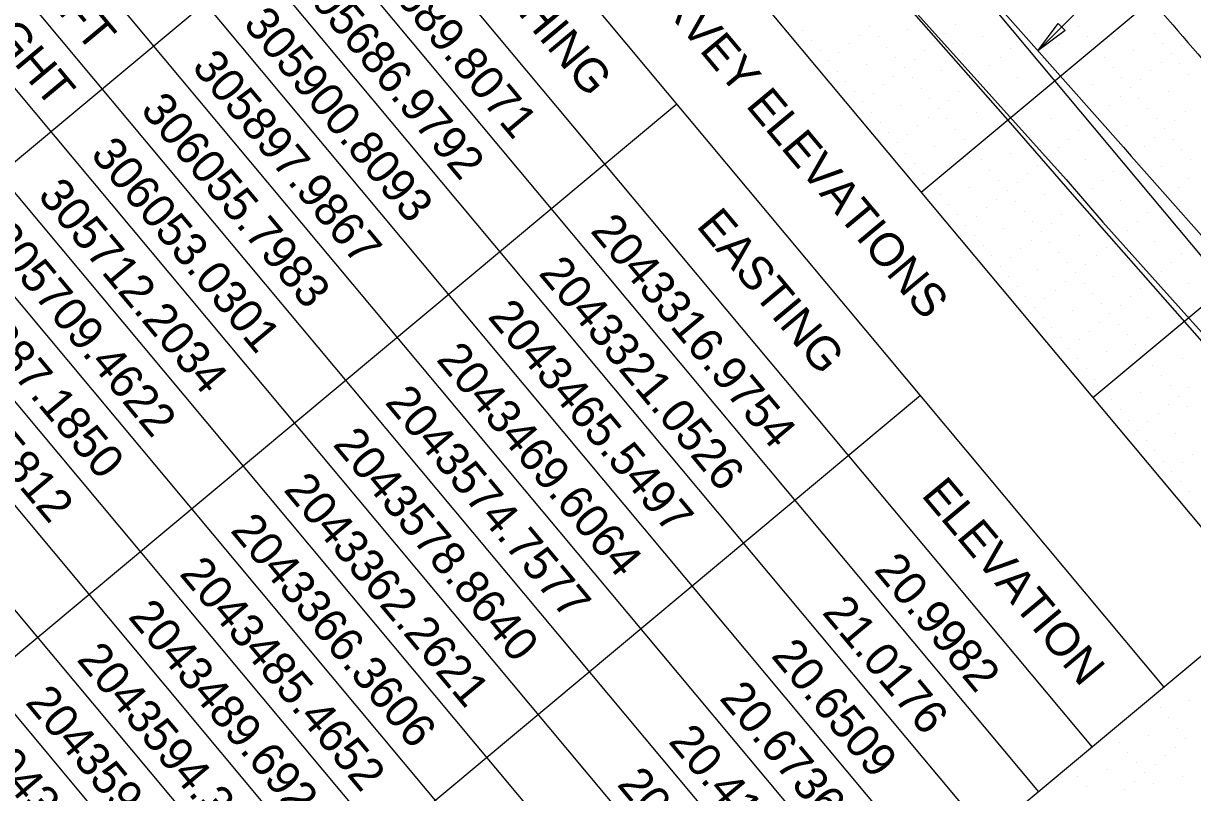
# Model space of a CAD drawing. Extents: x 2042995 to 2043795, y 305365 to 306249.
# Drawn here: x 2043107.3 to 2043194.7, y 305897.9 to 305955.5 of the extents above; entities that cross this region are included whole.
import ezdxf

# ---------------------------------------------------------------- set-up
doc = ezdxf.new("R2010")
doc.units = 0
for name, color, linetype in [('BR_AUTO DIMENSION', 7, 'Continuous'), ('BR_BORDER LINES', 7, 'Continuous'), ('BR_CONCRETE', 7, 'Continuous'), ('BR_EXIST_GROUND_CL', 7, 'Continuous'), ('BR_EXIST_GROUND_LT', 7, 'Continuous'), ('BR_EXIST_GROUND_RT', 7, 'Continuous'), ('BR_GRID DOTS', 7, 'Continuous'), ('BR_GRID LINES', 7, 'Continuous'), ('BR_TABLE LINES', 7, 'Continuous'), ('BR_TEXT', 7, 'Continuous')]:
    doc.layers.add(name, color=color, linetype=linetype)

msp = doc.modelspace()

# ---------------------------------------------------------------- linework, layer by layer
at = {"layer": 'BR_AUTO DIMENSION'}
msp.add_line((2043190.687, 305960.982), (2043183.14, 305953.414), dxfattribs=at)
msp.add_lwpolyline([(2043185.171, 305954.92), (2043183.14, 305953.414), (2043184.64, 305955.449)], close=True, dxfattribs=at)
at = {"layer": 'BR_BORDER LINES'}
for p, q in [((2043123.144, 306004.214), (2043200.067, 305912.112)), ((2043200.067, 305912.112), (2043117.942, 305843.522))]:
    msp.add_line(p, q, dxfattribs=at)
at = {"layer": 'BR_CONCRETE'}
msp.add_spline([(2043139.109, 306017.548), (2043148.199, 306007.16), (2043160.233, 305993.368), (2043172.245, 305979.557), (2043184.234, 305965.727), (2043196.201, 305951.879), (2043208.145, 305938.012), (2043220.067, 305924.126), (2043231.966, 305910.221), (2043243.843, 305896.297), (2043255.698, 305882.355), (2043267.529, 305868.394), (2043279.339, 305854.414), (2043291.126, 305840.415), (2043302.89, 305826.398), (2043314.632, 305812.361), (2043326.352, 305798.306), (2043338.049, 305784.233), (2043349.724, 305770.14), (2043361.376, 305756.029), (2043373.005, 305741.899), (2043384.613, 305727.75), (2043396.197, 305713.582), (2043407.76, 305699.396), (2043419.299, 305685.191), (2043430.817, 305670.967), (2043442.311, 305656.724), (2043453.784, 305642.463), (2043465.234, 305628.182), (2043476.661, 305613.883), (2043488.066, 305599.566), (2043499.448, 305585.229), (2043510.808, 305570.874), (2043522.146, 305556.5), (2043533.461, 305542.107), (2043544.753, 305527.695), (2043547.219, 305524.543)], degree=3, dxfattribs=at)
at = {"layer": 'BR_EXIST_GROUND_CL'}
msp.add_lwpolyline([(2043131.677, 306011.341), (2043140.193, 306001.792), (2043140.699, 306001.23), (2043156.38, 305983.649), (2043157.081, 305982.859), (2043172.95, 305964.927), (2043173.594, 305964.202), (2043189.52, 305946.204), (2043190.108, 305945.543), (2043206.09, 305927.482)], dxfattribs=at)
at = {"layer": 'BR_EXIST_GROUND_LT'}
msp.add_lwpolyline([(2043127.956, 306008.234), (2043136.17, 305998.877), (2043139.136, 305995.79), (2043151.989, 305981.161), (2043154.962, 305977.692), (2043168.609, 305962.472), (2043171.467, 305959.143), (2043185.235, 305943.789), (2043187.984, 305940.592), (2043201.866, 305925.112), (2043204.513, 305922.037), (2043218.502, 305906.439), (2043218.632, 305906.288), (2043219.569, 305905.47), (2043220.034, 305904.951), (2043224.372, 305899.652), (2043230.892, 305893.533)], dxfattribs=at)
at = {"layer": 'BR_EXIST_GROUND_RT'}
msp.add_lwpolyline([(2043127.871, 306008.162), (2043135.626, 305999.492), (2043140.757, 305993.755), (2043152.231, 305980.926), (2043152.788, 305980.304), (2043164.384, 305967.114), (2043169.234, 305961.496), (2043181.072, 305948.031), (2043185.685, 305942.691), (2043197.744, 305928.975)], dxfattribs=at)
at = {"layer": 'BR_GRID DOTS'}
for p, q in [((2043164.169, 305955.093), (2043164.169, 305955.093)), ((2043165.578, 305954.966), (2043165.578, 305954.966)), ((2043169.803, 305954.587), (2043169.803, 305954.587)), ((2043170.571, 305955.228), (2043170.571, 305955.228)), ((2043173.388, 305954.975), (2043173.388, 305954.975)), ((2043176.205, 305954.722), (2043176.205, 305954.722)), ((2043176.973, 305955.363), (2043176.973, 305955.363)), ((2043182.607, 305954.857), (2043182.607, 305954.857)), ((2043186.191, 305955.245), (2043186.191, 305955.245)), ((2043191.826, 305954.739), (2043191.826, 305954.739)), ((2043166.219, 305954.199), (2043166.219, 305954.199)), ((2043169.036, 305953.946), (2043169.036, 305953.946)), ((2043171.212, 305954.46), (2043171.212, 305954.46)), ((2043171.853, 305953.693), (2043171.853, 305953.693)), ((2043175.438, 305954.081), (2043175.438, 305954.081)), ((2043176.846, 305953.954), (2043176.846, 305953.954)), ((2043179.022, 305954.469), (2043179.022, 305954.469)), ((2043181.839, 305954.216), (2043181.839, 305954.216)), ((2043184.656, 305953.963), (2043184.656, 305953.963)), ((2043186.832, 305954.477), (2043186.832, 305954.477)), ((2043192.467, 305953.971), (2043192.467, 305953.971)), ((2043193.875, 305953.845), (2043193.875, 305953.845)), ((2043194.643, 305954.486), (2043194.643, 305954.486)), ((2043166.86, 305953.431), (2043166.86, 305953.431)), ((2043168.268, 305953.305), (2043168.268, 305953.305)), ((2043172.494, 305952.925), (2043172.494, 305952.925)), ((2043173.903, 305952.799), (2043173.903, 305952.799)), ((2043174.67, 305953.44), (2043174.67, 305953.44)), ((2043177.487, 305953.187), (2043177.487, 305953.187)), ((2043180.304, 305952.934), (2043180.304, 305952.934)), ((2043181.072, 305953.575), (2043181.072, 305953.575)), ((2043188.115, 305952.942), (2043188.115, 305952.942)), ((2043190.291, 305953.457), (2043190.291, 305953.457)), ((2043193.108, 305953.204), (2043193.108, 305953.204)), ((2043166.733, 305952.023), (2043166.733, 305952.023)), ((2043167.501, 305952.664), (2043167.501, 305952.664)), ((2043168.142, 305951.896), (2043168.142, 305951.896)), ((2043170.318, 305952.411), (2043170.318, 305952.411)), ((2043173.135, 305952.158), (2043173.135, 305952.158)), ((2043175.952, 305951.905), (2043175.952, 305951.905)), ((2043178.128, 305952.419), (2043178.128, 305952.419)), ((2043179.537, 305952.293), (2043179.537, 305952.293)), ((2043188.756, 305952.175), (2043188.756, 305952.175)), ((2043191.573, 305951.922), (2043191.573, 305951.922)), ((2043192.34, 305952.563), (2043192.34, 305952.563)), ((2043193.749, 305952.436), (2043193.749, 305952.436)), ((2043168.783, 305951.129), (2043168.783, 305951.129)), ((2043172.368, 305951.517), (2043172.368, 305951.517)), ((2043173.776, 305951.39), (2043173.776, 305951.39)), ((2043178.002, 305951.011), (2043178.002, 305951.011)), ((2043178.769, 305951.652), (2043178.769, 305951.652)), ((2043181.586, 305951.399), (2043181.586, 305951.399)), ((2043189.397, 305951.407), (2043189.397, 305951.407)), ((2043190.805, 305951.281), (2043190.805, 305951.281)), ((2043194.39, 305951.669), (2043194.39, 305951.669)), ((2043169.424, 305950.361), (2043169.424, 305950.361)), ((2043170.833, 305950.235), (2043170.833, 305950.235)), ((2043171.6, 305950.876), (2043171.6, 305950.876)), ((2043174.417, 305950.623), (2043174.417, 305950.623)), ((2043177.234, 305950.37), (2043177.234, 305950.37)), ((2043179.41, 305950.884), (2043179.41, 305950.884)), ((2043187.221, 305950.893), (2043187.221, 305950.893)), ((2043190.038, 305950.64), (2043190.038, 305950.64)), ((2043192.855, 305950.387), (2043192.855, 305950.387)), ((2043170.065, 305949.594), (2043170.065, 305949.594)), ((2043172.882, 305949.341), (2043172.882, 305949.341)), ((2043175.058, 305949.855), (2043175.058, 305949.855)), ((2043176.467, 305949.729), (2043176.467, 305949.729)), ((2043180.051, 305950.117), (2043180.051, 305950.117)), ((2043180.692, 305949.349), (2043180.692, 305949.349)), ((2043188.503, 305949.358), (2043188.503, 305949.358)), ((2043189.27, 305949.999), (2043189.27, 305949.999)), ((2043190.679, 305949.872), (2043190.679, 305949.872)), ((2043169.297, 305948.953), (2043169.297, 305948.953)), ((2043170.706, 305948.826), (2043170.706, 305948.826)), ((2043174.932, 305948.447), (2043174.932, 305948.447)), ((2043175.699, 305949.088), (2043175.699, 305949.088)), ((2043178.516, 305948.835), (2043178.516, 305948.835)), ((2043187.735, 305948.717), (2043187.735, 305948.717)), ((2043191.32, 305949.105), (2043191.32, 305949.105)), ((2043194.137, 305948.852), (2043194.137, 305948.852)), ((2043171.347, 305948.059), (2043171.347, 305948.059)), ((2043174.164, 305947.806), (2043174.164, 305947.806)), ((2043176.34, 305948.32), (2043176.34, 305948.32)), ((2043176.981, 305947.553), (2043176.981, 305947.553)), ((2043181.974, 305947.814), (2043181.974, 305947.814)), ((2043184.15, 305948.329), (2043184.15, 305948.329)), ((2043186.968, 305948.076), (2043186.968, 305948.076)), ((2043189.785, 305947.823), (2043189.785, 305947.823)), ((2043191.961, 305948.337), (2043191.961, 305948.337)), ((2043192.602, 305947.57), (2043192.602, 305947.57)), ((2043193.369, 305948.211), (2043193.369, 305948.211)), ((2043171.988, 305947.291), (2043171.988, 305947.291)), ((2043173.397, 305947.165), (2043173.397, 305947.165)), ((2043177.622, 305946.785), (2043177.622, 305946.785)), ((2043182.615, 305947.047), (2043182.615, 305947.047)), ((2043185.433, 305946.794), (2043185.433, 305946.794)), ((2043186.2, 305947.435), (2043186.2, 305947.435)), ((2043191.834, 305946.929), (2043191.834, 305946.929)), ((2043193.243, 305946.802), (2043193.243, 305946.802)), ((2043171.862, 305945.882), (2043171.862, 305945.882)), ((2043172.629, 305946.524), (2043172.629, 305946.524)), ((2043175.446, 305946.271), (2043175.446, 305946.271)), ((2043183.256, 305946.279), (2043183.256, 305946.279)), ((2043184.665, 305946.153), (2043184.665, 305946.153)), ((2043191.067, 305946.288), (2043191.067, 305946.288)), ((2043193.884, 305946.035), (2043193.884, 305946.035)), ((2043173.27, 305945.756), (2043173.27, 305945.756)), ((2043173.911, 305944.988), (2043173.911, 305944.988)), ((2043178.904, 305945.25), (2043178.904, 305945.25)), ((2043181.08, 305945.765), (2043181.08, 305945.765)), ((2043183.897, 305945.512), (2043183.897, 305945.512)), ((2043186.715, 305945.259), (2043186.715, 305945.259)), ((2043189.532, 305945.006), (2043189.532, 305945.006)), ((2043190.299, 305945.647), (2043190.299, 305945.647)), ((2043194.525, 305945.267), (2043194.525, 305945.267)), ((2043174.552, 305944.221), (2043174.552, 305944.221)), ((2043179.545, 305944.483), (2043179.545, 305944.483)), ((2043182.362, 305944.23), (2043182.362, 305944.23)), ((2043183.13, 305944.871), (2043183.13, 305944.871)), ((2043184.538, 305944.744), (2043184.538, 305944.744)), ((2043188.764, 305944.365), (2043188.764, 305944.365)), ((2043192.349, 305944.753), (2043192.349, 305944.753)), ((2043178.01, 305943.2), (2043178.01, 305943.2)), ((2043180.186, 305943.715), (2043180.186, 305943.715)), ((2043181.595, 305943.588), (2043181.595, 305943.588)), ((2043185.18, 305943.977), (2043185.18, 305943.977)), ((2043185.821, 305943.209), (2043185.821, 305943.209)), ((2043187.997, 305943.724), (2043187.997, 305943.724)), ((2043193.631, 305943.218), (2043193.631, 305943.218)), ((2043194.398, 305943.859), (2043194.398, 305943.859)), ((2043175.834, 305942.686), (2043175.834, 305942.686)), ((2043180.06, 305942.306), (2043180.06, 305942.306)), ((2043180.827, 305942.947), (2043180.827, 305942.947)), ((2043183.644, 305942.694), (2043183.644, 305942.694)), ((2043186.462, 305942.441), (2043186.462, 305942.441)), ((2043187.229, 305943.083), (2043187.229, 305943.083)), ((2043192.863, 305942.577), (2043192.863, 305942.577)), ((2043176.475, 305941.918), (2043176.475, 305941.918)), ((2043179.292, 305941.665), (2043179.292, 305941.665)), ((2043181.468, 305942.18), (2043181.468, 305942.18)), ((2043182.109, 305941.412), (2043182.109, 305941.412)), ((2043185.694, 305941.8), (2043185.694, 305941.8)), ((2043187.103, 305941.674), (2043187.103, 305941.674)), ((2043189.279, 305942.189), (2043189.279, 305942.189)), ((2043192.096, 305941.936), (2043192.096, 305941.936)), ((2043177.116, 305941.151), (2043177.116, 305941.151)), ((2043178.525, 305941.024), (2043178.525, 305941.024)), ((2043182.75, 305940.645), (2043182.75, 305940.645)), ((2043184.927, 305941.159), (2043184.927, 305941.159)), ((2043187.744, 305940.906), (2043187.744, 305940.906)), ((2043190.561, 305940.653), (2043190.561, 305940.653)), ((2043191.328, 305941.294), (2043191.328, 305941.294)), ((2043176.99, 305939.742), (2043176.99, 305939.742)), ((2043177.757, 305940.383), (2043177.757, 305940.383)), ((2043180.574, 305940.13), (2043180.574, 305940.13)), ((2043183.391, 305939.877), (2043183.391, 305939.877)), ((2043184.159, 305940.518), (2043184.159, 305940.518)), ((2043188.385, 305940.139), (2043188.385, 305940.139)), ((2043189.793, 305940.012), (2043189.793, 305940.012)), ((2043178.398, 305939.616), (2043178.398, 305939.616)), ((2043179.039, 305938.848), (2043179.039, 305938.848)), ((2043182.624, 305939.236), (2043182.624, 305939.236)), ((2043184.033, 305939.11), (2043184.033, 305939.11)), ((2043186.209, 305939.624), (2043186.209, 305939.624)), ((2043189.026, 305939.371), (2043189.026, 305939.371)), ((2043191.843, 305939.118), (2043191.843, 305939.118)), ((2043194.66, 305938.865), (2043194.66, 305938.865)), ((2043179.68, 305938.081), (2043179.68, 305938.081)), ((2043181.089, 305937.954), (2043181.089, 305937.954)), ((2043181.856, 305938.595), (2043181.856, 305938.595)), ((2043184.674, 305938.342), (2043184.674, 305938.342)), ((2043187.491, 305938.089), (2043187.491, 305938.089)), ((2043188.258, 305938.73), (2043188.258, 305938.73)), ((2043189.667, 305938.604), (2043189.667, 305938.604)), ((2043193.892, 305938.224), (2043193.892, 305938.224)), ((2043180.321, 305937.313), (2043180.321, 305937.313)), ((2043183.139, 305937.06), (2043183.139, 305937.06)), ((2043185.315, 305937.575), (2043185.315, 305937.575)), ((2043186.723, 305937.448), (2043186.723, 305937.448)), ((2043190.308, 305937.836), (2043190.308, 305937.836)), ((2043190.949, 305937.069), (2043190.949, 305937.069)), ((2043193.125, 305937.583), (2043193.125, 305937.583)), ((2043179.554, 305936.672), (2043179.554, 305936.672)), ((2043180.962, 305936.546), (2043180.962, 305936.546)), ((2043185.188, 305936.166), (2043185.188, 305936.166)), ((2043185.956, 305936.807), (2043185.956, 305936.807)), ((2043188.773, 305936.554), (2043188.773, 305936.554)), ((2043191.59, 305936.301), (2043191.59, 305936.301)), ((2043192.357, 305936.942), (2043192.357, 305936.942)), ((2043181.603, 305935.778), (2043181.603, 305935.778)), ((2043184.421, 305935.525), (2043184.421, 305935.525)), ((2043186.597, 305936.04), (2043186.597, 305936.04)), ((2043190.822, 305935.66), (2043190.822, 305935.66)), ((2043192.231, 305935.534), (2043192.231, 305935.534)), ((2043194.407, 305936.048), (2043194.407, 305936.048)), ((2043182.244, 305935.011), (2043182.244, 305935.011)), ((2043183.653, 305934.884), (2043183.653, 305934.884)), ((2043187.238, 305935.272), (2043187.238, 305935.272)), ((2043187.879, 305934.505), (2043187.879, 305934.505)), ((2043190.055, 305935.019), (2043190.055, 305935.019)), ((2043192.872, 305934.766), (2043192.872, 305934.766)), ((2043182.118, 305933.602), (2043182.118, 305933.602)), ((2043182.886, 305934.243), (2043182.886, 305934.243)), ((2043185.703, 305933.99), (2043185.703, 305933.99)), ((2043188.52, 305933.737), (2043188.52, 305933.737)), ((2043189.287, 305934.378), (2043189.287, 305934.378)), ((2043193.513, 305933.999), (2043193.513, 305933.999)), ((2043183.527, 305933.476), (2043183.527, 305933.476)), ((2043184.168, 305932.708), (2043184.168, 305932.708)), ((2043187.752, 305933.096), (2043187.752, 305933.096)), ((2043189.161, 305932.97), (2043189.161, 305932.97)), ((2043191.337, 305933.484), (2043191.337, 305933.484)), ((2043184.809, 305931.941), (2043184.809, 305931.941)), ((2043186.217, 305931.814), (2043186.217, 305931.814)), ((2043186.985, 305932.455), (2043186.985, 305932.455)), ((2043189.802, 305932.202), (2043189.802, 305932.202)), ((2043185.45, 305931.173), (2043185.45, 305931.173)), ((2043188.267, 305930.92), (2043188.267, 305930.92)), ((2043190.443, 305931.435), (2043190.443, 305931.435)), ((2043184.682, 305930.532), (2043184.682, 305930.532)), ((2043186.091, 305930.406), (2043186.091, 305930.406)), ((2043193.901, 305930.414), (2043193.901, 305930.414)), ((2043186.732, 305929.638), (2043186.732, 305929.638)), ((2043191.725, 305929.9), (2043191.725, 305929.9)), ((2043187.373, 305928.871), (2043187.373, 305928.871)), ((2043192.366, 305929.132), (2043192.366, 305929.132)), ((2043193.007, 305928.365), (2043193.007, 305928.365)), ((2043190.831, 305927.85), (2043190.831, 305927.85)), ((2043193.648, 305927.597), (2043193.648, 305927.597)), ((2043194.415, 305928.238), (2043194.415, 305928.238)), ((2043188.655, 305927.336), (2043188.655, 305927.336)), ((2043189.296, 305926.568), (2043189.296, 305926.568)), ((2043192.88, 305926.956), (2043192.88, 305926.956)), ((2043194.289, 305926.83), (2043194.289, 305926.83)), ((2043189.937, 305925.801), (2043189.937, 305925.801)), ((2043192.113, 305926.315), (2043192.113, 305926.315)), ((2043190.578, 305925.033), (2043190.578, 305925.033)), ((2043191.345, 305925.674), (2043191.345, 305925.674)), ((2043189.81, 305924.392), (2043189.81, 305924.392)), ((2043191.219, 305924.265), (2043191.219, 305924.265)), ((2043193.395, 305924.78), (2043193.395, 305924.78)), ((2043191.86, 305923.498), (2043191.86, 305923.498)), ((2043194.677, 305923.245), (2043194.677, 305923.245)), ((2043192.501, 305922.73), (2043192.501, 305922.73)), ((2043193.909, 305922.604), (2043193.909, 305922.604)), ((2043192.374, 305921.322), (2043192.374, 305921.322)), ((2043193.142, 305921.963), (2043193.142, 305921.963)), ((2043193.783, 305921.195), (2043193.783, 305921.195)), ((2043194.424, 305920.428), (2043194.424, 305920.428)), ((2043194.441, 305904.807), (2043194.441, 305904.807)), ((2043192.265, 305904.293), (2043192.265, 305904.293)), ((2043192.906, 305903.525), (2043192.906, 305903.525)), ((2043191.371, 305902.243), (2043191.371, 305902.243)), ((2043193.547, 305902.758), (2043193.547, 305902.758)), ((2043189.195, 305901.729), (2043189.195, 305901.729)), ((2043193.421, 305901.349), (2043193.421, 305901.349)), ((2043194.188, 305901.99), (2043194.188, 305901.99)), ((2043189.836, 305900.961), (2043189.836, 305900.961)), ((2043192.653, 305900.708), (2043192.653, 305900.708)), ((2043188.301, 305899.679), (2043188.301, 305899.679)), ((2043190.477, 305900.194), (2043190.477, 305900.194)), ((2043191.886, 305900.067), (2043191.886, 305900.067)), ((2043186.125, 305899.165), (2043186.125, 305899.165)), ((2043190.351, 305898.785), (2043190.351, 305898.785)), ((2043191.118, 305899.426), (2043191.118, 305899.426)), ((2043191.759, 305898.659), (2043191.759, 305898.659)), ((2043193.935, 305899.173), (2043193.935, 305899.173)), ((2043186.766, 305898.397), (2043186.766, 305898.397)), ((2043189.583, 305898.144), (2043189.583, 305898.144))]:
    msp.add_line(p, q, dxfattribs=at)
at = {"layer": 'BR_GRID LINES'}
for p, q in [((2043122.438, 306025.339), (2043554.061, 305508.544)), ((2043245.805, 306002.428), (2043174.426, 305942.812)), ((2043258.625, 305987.077), (2043187.246, 305927.462))]:
    msp.add_line(p, q, dxfattribs=at)
at = {"layer": 'BR_TABLE LINES'}
for p, q in [((2043115.631, 305997.939), (2043192.554, 305905.837)), ((2043123.72, 305977.334), (2043187.182, 305901.35)), ((2043087.07, 305974.086), (2043163.993, 305881.983)), ((2043119.72, 305973.993), (2043183.181, 305898.009)), ((2043137.956, 305971.209), (2043063.344, 305908.893)), ((2043115.882, 305970.788), (2043179.344, 305894.804)), ((2043112.045, 305967.583), (2043175.506, 305891.599)), ((2043108.207, 305964.378), (2043171.669, 305888.394)), ((2043104.369, 305961.173), (2043167.831, 305885.189)), ((2043064.045, 305954.855), (2043140.968, 305862.753)), ((2043096.694, 305954.763), (2043160.156, 305878.778)), ((2043092.857, 305951.558), (2043156.318, 305875.573)), ((2043156.156, 305949.418), (2043081.544, 305887.103)), ((2043089.019, 305948.352), (2043152.481, 305872.368)), ((2043085.181, 305945.147), (2043148.643, 305869.163)), ((2043081.344, 305941.942), (2043144.805, 305865.958)), ((2043174.355, 305927.628), (2043099.743, 305865.312))]:
    msp.add_line(p, q, dxfattribs=at)

# ---------------------------------------------------------------- texts
at = {"layer": 'BR_TEXT'}
for s, p in [('TOP OF RAIL SURVEY ELEVATIONS', (2043137.912, 305977.242)), ('NORTHING', (2043138.166, 305963.509)), ('305689.8071', (2043131.481, 305961.655)), ('LEFT', (2043107.254, 305959.463)), ('305686.9792', (2043127.537, 305958.577)), ('RIGHT', (2043102.78, 305957.019)), ('305900.8093', (2043123.7, 305955.372)), ('305897.9867', (2043119.862, 305952.167)), ('306055.7983', (2043116.024, 305948.962)), ('306053.0301', (2043112.293, 305945.63)), ('305712.2034', (2043108.349, 305942.552)), ('EASTING', (2043157.552, 305940.298)), ('305709.4622', (2043104.512, 305939.346)), ('2043316.9754', (2043149.636, 305939.917)), ('2043321.0526', (2043145.768, 305936.749)), ('305887.1850', (2043100.624, 305936.202)), ('2043465.5497', (2043141.961, 305933.507)), ('305884.5812', (2043096.836, 305932.936)), ('2043469.6064', (2043138.123, 305930.302)), ('2043574.7577', (2043134.286, 305927.097)), ('2043578.8640', (2043130.398, 305923.952)), ('2043362.2621', (2043126.717, 305920.56)), ('ELEVATION', (2043174.366, 305920.167)), ('2043366.3606', (2043122.743, 305917.518)), ('2043485.4652', (2043118.935, 305914.276)), ('20.9982', (2043170.817, 305914.557)), ('21.0176', (2043166.949, 305911.388)), ('2043489.6924', (2043115.098, 305911.071)), ('2043594.3292', (2043111.26, 305907.866)), ('20.6509', (2043163.142, 305908.146)), ('2043598.2912', (2043107.423, 305904.661)), ('20.6736', (2043159.274, 305904.977)), ('20.4188', (2043155.467, 305901.736)), ('2043374.7622', (2043103.585, 305901.456)), ('2043378.9226', (2043099.717, 305898.287)), ('20.4247', (2043151.629, 305898.531))]:
    msp.add_text(s, height=2.5, rotation=309.86836, dxfattribs=at).set_placement(p)

doc.saveas('drawing.dxf')
